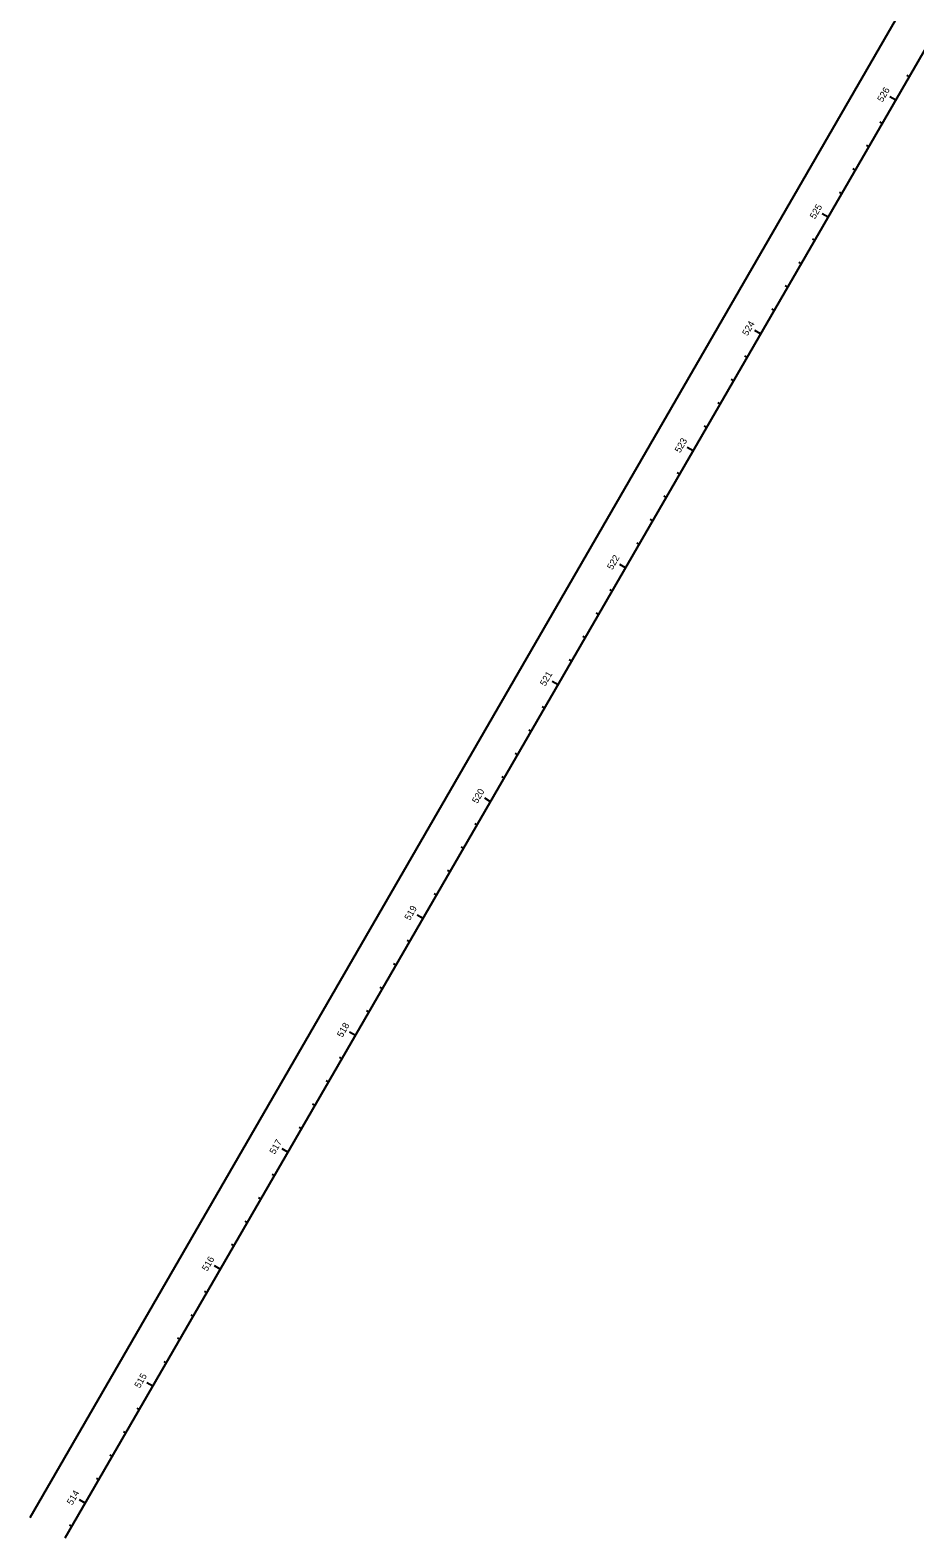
# Model space of a CAD drawing. Extents: x 2003883 to 2007688, y 399149 to 412300.
# Drawn here: x 2004790 to 2005445, y 399149 to 400266 of the extents above; entities that cross this region are included whole.
import ezdxf

# ---------------------------------------------------------------- set-up
doc = ezdxf.new("R2010")
doc.units = 0
for name, color, linetype in [('BaselineSurvey', 7, 'Continuous'), ('ConstLines', 7, 'Continuous'), ('Default', 7, 'Continuous'), ('TextAlgnStation100', 7, 'Continuous'), ('TextAlgnStation1000', 7, 'Continuous'), ('TextAlgnStation500', 7, 'Continuous'), ('TextAlgnTicks100', 7, 'Continuous'), ('TextAlgnTicks1000', 7, 'Continuous'), ('TextAlgnTicks500', 7, 'Continuous'), ('TextAlgnTicks5000', 7, 'Continuous')]:
    doc.layers.add(name, color=color, linetype=linetype)

msp = doc.modelspace()

# ---------------------------------------------------------------- linework, layer by layer
at = {"layer": 'BaselineSurvey'}
msp.add_line((2004815.7, 399149), (2006095.1, 401364.2), dxfattribs=at)
at = {"layer": 'ConstLines'}
msp.add_line((2004789.7, 399164), (2006069.1, 401379.2), dxfattribs=at)
at = {"layer": 'Default'}
msp.add_line((2004815.7, 399149), (2006095.1, 401364.2), dxfattribs=at)
at = {"layer": 'TextAlgnTicks100'}
for p, q in [((2005440.7, 400231.1), (2005438.9, 400232.1)), ((2005430.7, 400213.8), (2005426.3, 400216.3)), ((2005420.7, 400196.5), (2005418.9, 400197.5)), ((2005410.7, 400179.2), (2005408.9, 400180.2)), ((2005400.7, 400161.9), (2005398.9, 400162.9)), ((2005390.7, 400144.5), (2005388.9, 400145.5)), ((2005380.7, 400127.2), (2005376.3, 400129.7)), ((2005370.7, 400109.9), (2005368.9, 400110.9)), ((2005360.7, 400092.6), (2005358.9, 400093.6)), ((2005350.6, 400075.3), (2005348.9, 400076.3)), ((2005340.6, 400057.9), (2005338.9, 400058.9)), ((2005330.6, 400040.6), (2005326.3, 400043.1)), ((2005320.6, 400023.3), (2005318.9, 400024.3)), ((2005310.6, 400006), (2005308.9, 400007)), ((2005300.6, 399988.7), (2005298.9, 399989.7)), ((2005290.6, 399971.3), (2005288.9, 399972.3)), ((2005280.6, 399954), (2005276.3, 399956.5)), ((2005270.6, 399936.7), (2005268.9, 399937.7)), ((2005260.6, 399919.4), (2005258.9, 399920.4)), ((2005250.6, 399902.1), (2005248.9, 399903.1)), ((2005240.6, 399884.7), (2005238.9, 399885.7)), ((2005230.6, 399867.4), (2005226.3, 399869.9)), ((2005220.6, 399850.1), (2005218.9, 399851.1)), ((2005210.6, 399832.8), (2005208.9, 399833.8)), ((2005200.6, 399815.5), (2005198.9, 399816.5)), ((2005190.6, 399798.2), (2005188.9, 399799.2)), ((2005180.6, 399780.8), (2005176.3, 399783.3)), ((2005170.6, 399763.5), (2005168.9, 399764.5)), ((2005160.6, 399746.2), (2005158.9, 399747.2)), ((2005150.6, 399728.9), (2005148.9, 399729.9)), ((2005140.6, 399711.6), (2005138.9, 399712.6)), ((2005130.6, 399694.2), (2005126.3, 399696.7)), ((2005120.6, 399676.9), (2005118.9, 399677.9)), ((2005110.6, 399659.6), (2005108.9, 399660.6)), ((2005100.6, 399642.3), (2005098.8, 399643.3)), ((2005090.6, 399625), (2005088.8, 399626)), ((2005080.6, 399607.6), (2005076.2, 399610.1)), ((2005070.6, 399590.3), (2005068.8, 399591.3)), ((2005060.6, 399573), (2005058.8, 399574)), ((2005050.6, 399555.7), (2005048.8, 399556.7)), ((2005040.6, 399538.4), (2005038.8, 399539.4)), ((2005030.6, 399521), (2005026.2, 399523.5)), ((2005020.6, 399503.7), (2005018.8, 399504.7)), ((2005010.6, 399486.4), (2005008.8, 399487.4)), ((2005000.6, 399469.1), (2004998.8, 399470.1)), ((2004990.6, 399451.8), (2004988.8, 399452.8)), ((2004980.5, 399434.5), (2004976.2, 399437)), ((2004970.5, 399417.1), (2004968.8, 399418.1)), ((2004960.5, 399399.8), (2004958.8, 399400.8)), ((2004950.5, 399382.5), (2004948.8, 399383.5)), ((2004940.5, 399365.2), (2004938.8, 399366.2)), ((2004930.5, 399347.9), (2004926.2, 399350.4)), ((2004920.5, 399330.5), (2004918.8, 399331.5)), ((2004910.5, 399313.2), (2004908.8, 399314.2)), ((2004900.5, 399295.9), (2004898.8, 399296.9)), ((2004890.5, 399278.6), (2004888.8, 399279.6)), ((2004880.5, 399261.3), (2004876.2, 399263.8)), ((2004870.5, 399243.9), (2004868.8, 399244.9)), ((2004860.5, 399226.6), (2004858.8, 399227.6)), ((2004850.5, 399209.3), (2004848.8, 399210.3)), ((2004840.5, 399192), (2004838.8, 399193)), ((2004830.5, 399174.7), (2004826.2, 399177.2)), ((2004820.5, 399157.4), (2004818.8, 399158.4))]:
    msp.add_line(p, q, dxfattribs=at)
at = {"layer": 'TextAlgnTicks1000'}
for p, q in [((2005430.7, 400213.8), (2005428.9, 400214.8)), ((2005330.6, 400040.6), (2005328.9, 400041.6)), ((2005230.6, 399867.4), (2005228.9, 399868.4)), ((2005130.6, 399694.2), (2005126.3, 399696.7)), ((2005030.6, 399521), (2005028.8, 399522)), ((2004930.5, 399347.9), (2004928.8, 399348.9)), ((2004830.5, 399174.7), (2004828.8, 399175.7))]:
    msp.add_line(p, q, dxfattribs=at)
at = {"layer": 'TextAlgnTicks500'}
for p, q in [((2005430.7, 400213.8), (2005428.9, 400214.8)), ((2005380.7, 400127.2), (2005376.3, 400129.7)), ((2005330.6, 400040.6), (2005328.9, 400041.6)), ((2005280.6, 399954), (2005278.9, 399955)), ((2005230.6, 399867.4), (2005228.9, 399868.4)), ((2005180.6, 399780.8), (2005178.9, 399781.8)), ((2005130.6, 399694.2), (2005126.3, 399696.7)), ((2005080.6, 399607.6), (2005078.8, 399608.6)), ((2005030.6, 399521), (2005028.8, 399522)), ((2004980.5, 399434.5), (2004978.8, 399435.5)), ((2004930.5, 399347.9), (2004928.8, 399348.9)), ((2004880.5, 399261.3), (2004876.2, 399263.8)), ((2004830.5, 399174.7), (2004828.8, 399175.7))]:
    msp.add_line(p, q, dxfattribs=at)
at = {"layer": 'TextAlgnTicks5000'}
msp.add_line((2005130.6, 399694.2), (2005128.9, 399695.2), dxfattribs=at)

# ---------------------------------------------------------------- texts
at = {"layer": 'TextAlgnStation100'}
for s, p in [('526', (2005420.9, 400211.9)), ('525', (2005370.9, 400125.3)), ('524', (2005320.9, 400038.8)), ('523', (2005270.9, 399952.1)), ('522', (2005220.8, 399865.5)), ('521', (2005171.1, 399779.3)), ('520', (2005120.8, 399692.4)), ('519', (2005070.8, 399605.8)), ('518', (2005020.8, 399519.1)), ('517', (2004970.8, 399432.6)), ('516', (2004920.8, 399346)), ('515', (2004870.8, 399259.4)), ('514', (2004820.8, 399172.8))]:
    msp.add_text(s, height=4.98, rotation=59.9911, dxfattribs=at).set_placement(p)
at = {"layer": 'TextAlgnStation1000'}
msp.add_text('520', height=4.98, rotation=59.9911, dxfattribs=at).set_placement((2005120.8, 399692.4))
at = {"layer": 'TextAlgnStation500'}
for s, p in [('525', (2005370.9, 400125.3)), ('520', (2005120.8, 399692.4)), ('515', (2004870.8, 399259.4))]:
    msp.add_text(s, height=4.98, rotation=59.9911, dxfattribs=at).set_placement(p)

doc.saveas('drawing.dxf')
